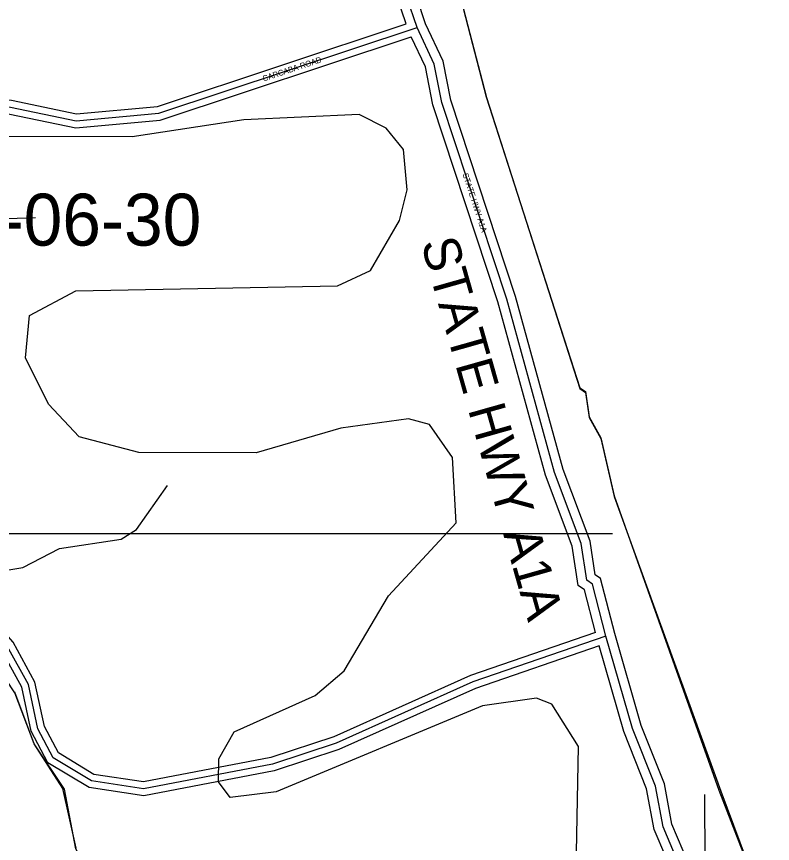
# Model space of a CAD drawing. Extents: x 418523 to 616617, y 1878279 to 2196743.
# Drawn here: x 559594 to 562868, y 2033859 to 2037441 of the extents above; entities that cross this region are included whole.
import ezdxf

# ---------------------------------------------------------------- set-up
doc = ezdxf.new("R2010")
doc.units = 0
for name, color, linetype in [('Level 1', 7, 'Continuous'), ('Level 2', 7, 'Continuous'), ('Level 22', 7, 'Continuous'), ('Level 23', 7, 'Continuous'), ('Level 28', 7, 'Continuous'), ('Level 31', 7, 'Continuous'), ('Level 32', 7, 'Continuous'), ('Level 34', 7, 'Continuous'), ('Level 5', 7, 'Continuous'), ('Level 7', 7, 'Continuous'), ('Level 8', 7, 'Continuous')]:
    doc.layers.add(name, color=color, linetype=linetype)

msp = doc.modelspace()

# ---------------------------------------------------------------- linework, layer by layer
at = {"layer": 'Level 1'}
for p, q in [((552189.176, 2035201.554), (562175.021, 2035201.312)), ((562597.423, 2029956.365), (562574.997, 2034070.471))]:
    msp.add_line(p, q, dxfattribs=at)
at = {"layer": 'Level 22'}
msp.add_line((561328.297, 2037393.436), (561114.884, 2038033.312), dxfattribs=at)
for points in [[(562146.35, 2034756.943), (562088.642, 2034982.199), (562063.66, 2034998.991), (562039.042, 2035157.248), (561923.264, 2035465.934), (561716.767, 2036216.705), (561435.785, 2037068.042), (561402.64, 2037234.686), (561328.297, 2037393.436)], [(562658.663, 2033054.775), (562443.921, 2033813.926), (562394.17, 2033930.791), (562361.356, 2034106.16), (562261.895, 2034356.251), (562146.35, 2034756.943)]]:
    msp.add_lwpolyline(points, dxfattribs=at)
at = {"layer": 'Level 23'}
for p, q in [((561365.509, 2037408.296), (561152.83, 2038045.967)), ((561280.85, 2037409.267), (561086.092, 2037993.211))]:
    msp.add_line(p, q, dxfattribs=at)
for points in [[(562184.951, 2034767.45), (562123.608, 2035006.893), (562100.495, 2035022.429), (562077.936, 2035167.452), (561961.352, 2035478.287), (561755.069, 2036228.285), (561474.539, 2037078.251), (561440.925, 2037247.251), (561365.509, 2037408.296)], [(562100.939, 2034773.019), (562053.675, 2034957.505), (562026.823, 2034975.554), (562000.147, 2035147.044), (561885.175, 2035453.581), (561678.465, 2036205.125), (561397.03, 2037057.834), (561364.355, 2037222.121), (561302.893, 2037353.365)], [(562697.01, 2033066.172), (562481.72, 2033827.258), (562432.685, 2033942.44), (562399.96, 2034117.334), (562299.787, 2034369.215), (562184.951, 2034767.45)], [(562612.699, 2033070.31), (562406.123, 2033800.595), (562355.654, 2033919.141), (562322.752, 2034094.986), (562224.002, 2034343.288), (562116.808, 2034715.022)]]:
    msp.add_lwpolyline(points, dxfattribs=at)
at = {"layer": 'Level 31'}
for points in [[(558917.116, 2036657.908), (558817.265, 2036749.817), (558833.98, 2036841.416), (558992.962, 2036949.363), (559243.17, 2037057.071), (559568.137, 2037047.845), (559851.479, 2036988.909), (560210.133, 2037021.421), (561328.297, 2037393.436)], [(562146.35, 2034756.943), (561570.57, 2034558.415), (560978.139, 2034293.026), (560702.62, 2034202.102), (560143.855, 2034095.196), (559918.712, 2034129.246), (559752.349, 2034229.691), (559686.155, 2034354.967), (559644.846, 2034546.727), (559553.739, 2034713.89), (559420.772, 2034864.071)]]:
    msp.add_lwpolyline(points, dxfattribs=at)
at = {"layer": 'Level 32'}
for points in [[(558896.799, 2036635.835), (558784.785, 2036738.94), (558806.724, 2036859.172), (558978.475, 2036975.789), (559237.395, 2037087.247), (559571.645, 2037077.758), (559853.217, 2037019.191), (560203.961, 2037050.986), (561280.85, 2037409.267)], [(558937.434, 2036679.981), (558849.745, 2036760.694), (558861.235, 2036823.66), (559007.45, 2036922.938), (559248.944, 2037026.894), (559564.63, 2037017.931), (559849.741, 2036958.628), (560216.304, 2036991.857), (561302.893, 2037353.365)], [(562100.939, 2034773.018), (561559.526, 2034586.341), (560967.277, 2034321.034), (560695.069, 2034231.201), (560143.261, 2034125.627), (559929.105, 2034158.016), (559774.984, 2034251.07), (559714.612, 2034365.327), (559673.262, 2034557.28), (559578.455, 2034731.231), (559443.235, 2034883.958)], [(562116.808, 2034715.022), (561581.615, 2034530.489), (560989, 2034265.017), (560710.171, 2034173.002), (560144.448, 2034064.764), (559908.32, 2034100.476), (559729.714, 2034208.313), (559657.698, 2034344.607), (559616.431, 2034536.174), (559529.024, 2034696.548), (559398.31, 2034844.183)]]:
    msp.add_lwpolyline(points, dxfattribs=at)
at = {"layer": 'Level 5'}
for points in [[(561530.034, 2037473.017), (561628.823, 2037089.219), (562033.265, 2035829.116), (562058.205, 2035812.345), (562074.518, 2035703.943), (562124.24, 2035612.081), (562181.816, 2035361.796), (562644.5, 2034084.822), (562867.655, 2033483.891)], [(558742.327, 2036431.661), (558934.191, 2036472.725), (559050.675, 2036405.634), (559092.157, 2036338.813), (559417.603, 2036446.14), (559476.352, 2036562.653), (559676.456, 2036570.336)], [(559471.389, 2035028.767), (559621.502, 2035053.29), (559780.195, 2035136.164), (560047.09, 2035176.957), (560113.91, 2035218.439), (560247.91, 2035409.756)], [(560712.827, 2032240.408), (560215.102, 2033000.61), (560066.451, 2033426.258), (559851.009, 2033835.425), (559801.843, 2034094.02), (559670.024, 2034290.608), (559586.431, 2034511.557), (559354.12, 2034862.432), (559296.255, 2035012.686)]]:
    msp.add_lwpolyline(points, dxfattribs=at)
at = {"layer": 'Level 7'}
msp.add_lwpolyline([(562018.43, 2033820.089), (562028.232, 2034278.56), (561912.116, 2034462.353), (561845.514, 2034487.552), (561611.999, 2034454.959), (560718.805, 2034082.741), (560518.63, 2034058.347), (560468.848, 2034125.208), (560469.166, 2034225.241), (560536.216, 2034341.754), (560886.871, 2034499.001), (561012.272, 2034606.976), (561205.051, 2034931.476), (561497.842, 2035247.306), (561482.077, 2035530.772), (561382.502, 2035672.824), (561290.9, 2035698.124), (560998.964, 2035657.39), (560631.837, 2035550.233), (560123.325, 2035551.867), (559865.088, 2035619.376), (559732.192, 2035761.547), (559632.776, 2035961.951), (559650.044, 2036145.286), (559850.476, 2036253), (560984.312, 2036274.343), (561126.225, 2036340.576), (561251.994, 2036556.903), (561285.762, 2036690.186), (561269.649, 2036865.31), (561194.915, 2036957.241), (561078.401, 2037015.991), (560578.15, 2036992.585), (560094.38, 2036919.128), (559369.123, 2036921.48)], dxfattribs=at)
at = {"layer": 'Level 8'}
for points in [[(561528.774, 2037476.157), (561627.783, 2037092.15), (562032.815, 2035832.126), (562057.815, 2035816.126), (562073.818, 2035707.123), (562123.82, 2035615.121), (562181.826, 2035365.116), (562635.86, 2034089.092), (562867.875, 2033488.081)], [(559851.799, 2033838.055), (559793.793, 2034096.06), (559670.024, 2034290.608), (559586.78, 2034514.067)]]:
    msp.add_lwpolyline(points, dxfattribs=at)

# ---------------------------------------------------------------- texts
at = {"layer": 'Level 2'}
msp.add_text('32-06-30', height=225, dxfattribs=at).set_placement((559189.611, 2036448.215))
at = {"layer": 'Level 28'}
msp.add_text('STATE HWY A1A', height=159.99916, rotation=285.793628, dxfattribs=at).set_placement((561344.313, 2036460.391))
at = {"layer": 'Level 34'}
for s, rotation, p in [('CARCABA ROAD', 18.401664, (560663.779, 2037159.179)), ('STATE HWY A1A', 288.2644, (561525.144, 2036757.421))]:
    msp.add_text(s, height=25, rotation=rotation, dxfattribs=at).set_placement(p)

doc.saveas('drawing.dxf')
